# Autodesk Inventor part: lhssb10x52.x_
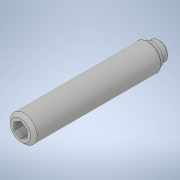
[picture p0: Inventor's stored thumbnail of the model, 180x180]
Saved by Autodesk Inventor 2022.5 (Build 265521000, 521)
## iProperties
Created: 2021-02
Part Number: lhssb10x52.x_
Material: 一般
Document SubType Name: Modeling
Designer: ImaoCorp
Density: 1 g/cm^3
Appearance: 既定
Sending System: SOLIDWORKS 2019-2019304
MC: AMD64
MC_MODEL: Intel64 Family 6 Model 60 Stepping 3, GenuineIntel
OS: Windows_NT
FRU: Parasolid Version 31.0, build 290,  9- 1-2019
FORMAT: text
GUISE: transmit
KEY: lhssb10x52
FILE: lhssb10x52.x_t
DATE: Mon Feb 22 14:55:51 2021
Author: ImaoCorp
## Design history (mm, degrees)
feature "Base1"
node "ソリッド1"
